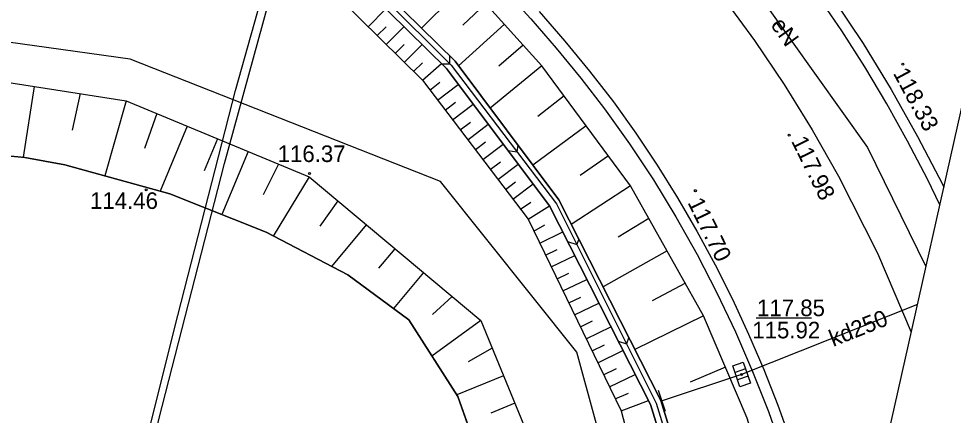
# Model space of a CAD drawing. Extents: x 6424617 to 6425697, y 5665845 to 5667190.
# Drawn here: x 6425523.12 to 6425565.32, y 5666883.53 to 5666901.46 of the extents above; entities that cross this region are included whole.
import ezdxf

# ---------------------------------------------------------------- set-up
doc = ezdxf.new("R2010")
doc.units = 0
for name, color, linetype in [('Warstwa 10', 7, 'Continuous'), ('Warstwa 12', 7, 'Continuous'), ('Warstwa 13', 7, 'Continuous'), ('Warstwa 14', 7, 'Continuous'), ('Warstwa 15', 7, 'Continuous'), ('Warstwa 2', 7, 'Continuous'), ('Warstwa 20', 7, 'Continuous'), ('Warstwa 21', 7, 'Continuous'), ('Warstwa 25', 7, 'Continuous'), ('Warstwa 4', 7, 'Continuous'), ('Warstwa 6', 7, 'Continuous'), ('Warstwa 63', 7, 'Continuous'), ('Warstwa 8', 7, 'Continuous'), ('Warstwa 9', 7, 'Continuous')]:
    doc.layers.add(name, color=color, linetype=linetype)

msp = doc.modelspace()

# ---------------------------------------------------------------- linework, layer by layer
at = {"layer": 'Warstwa 10'}
msp.add_lwpolyline([(6425511.502, 5666812.229), (6425512.943, 5666817.949), (6425515.607, 5666829.564), (6425516.724, 5666834.415), (6425518.245, 5666840.499), (6425520.445, 5666849.084), (6425523.479, 5666860.949), (6425527.047, 5666874.99), (6425530.311, 5666888.044), (6425532.912, 5666898.211), (6425534.329, 5666903.258)], dxfattribs=at)
at = {"layer": 'Warstwa 12'}
for points in [[(6425480.91, 5666946.73), (6425514.86, 5666932.41), (6425528.46, 5666925.91), (6425545.47, 5666915.06), (6425553.34, 5666907.03), (6425561.44, 5666895.63), (6425564.087, 5666890.255)], [(6425512.165, 5666813.402), (6425513.737, 5666820.109), (6425517.071, 5666834.688), (6425519.2, 5666843.022), (6425525.117, 5666866.017), (6425529.597, 5666883.929), (6425532.42, 5666894.918), (6425537.237, 5666912.487)], [(6425563.702, 5666888.538), (6425555.76, 5666885.38), (6425552.17, 5666884.18)]]:
    msp.add_lwpolyline(points, dxfattribs=at)
at = {"layer": 'Warstwa 14'}
msp.add_line((6425558.919, 5666887.928), (6425556.418, 5666887.928), dxfattribs=at)
msp.add_circle((6425555.76, 5666885.38), 0.045, dxfattribs=at)
at = {"layer": 'Warstwa 2'}
msp.add_lwpolyline([(6425506.88, 5666899.5), (6425503.781, 5666900.196), (6425486.964, 5666839.13), (6425494.478, 5666830.381), (6425496.276, 5666828.558), (6425500.644, 5666826.749), (6425510.918, 5666824.552), (6425520.412, 5666825.171), (6425529.858, 5666828.662), (6425537.889, 5666834.639), (6425544.658, 5666842.259), (6425549.605, 5666852.483), (6425550.773, 5666856.833), (6425551.852, 5666866.697), (6425550.934, 5666876.787), (6425548.326, 5666886.387), (6425542.173, 5666894.101), (6425528.149, 5666899.626), (6425515.187, 5666901.43), (6425512.303, 5666898.502), (6425510.878, 5666898.777)], dxfattribs=at)
at = {"layer": 'Warstwa 20'}
for points in [[(6425507.871, 5666925.02), (6425508.67, 5666920.18), (6425520.44, 5666914.46), (6425527.39, 5666910.43), (6425535.63, 5666904.32), (6425541.35, 5666898.67), (6425546.12, 5666892.4), (6425550.32, 5666883.74), (6425552.26, 5666876.31), (6425552.96, 5666866.55), (6425552.11, 5666856.38), (6425553.468, 5666853.734)], [(6425559.205, 5666868.481), (6425558.639, 5666873.647), (6425557.949, 5666876.96), (6425556.015, 5666883.397), (6425554.048, 5666888.034), (6425550.752, 5666893.896), (6425546.749, 5666899.32), (6425543.366, 5666903.082), (6425536.967, 5666908.8), (6425531.745, 5666912.645), (6425523.272, 5666917.6), (6425507.871, 5666925.02)], [(6425519.675, 5666899.039), (6425527.975, 5666897.748), (6425536.235, 5666894.308), (6425543.981, 5666887.816), (6425548.082, 5666877.839), (6425549.655, 5666866.937), (6425548.7, 5666857.221), (6425546.834, 5666855.804), (6425546.717, 5666855.426), (6425547.53, 5666853.351), (6425543.78, 5666845.666), (6425539.816, 5666839.966), (6425533.071, 5666833.755), (6425527.173, 5666830.091), (6425521.012, 5666827.921)]]:
    msp.add_lwpolyline(points, dxfattribs=at)
at = {"layer": 'Warstwa 21'}
msp.add_line((6425552.327, 5666883.705), (6425552.013, 5666884.655), dxfattribs=at)
for points in [[(6425553.468, 5666853.734), (6425554.21, 5666857.161), (6425554.915, 5666866.832), (6425553.95, 5666876.532), (6425551.644, 5666884.017), (6425547.085, 5666893.002), (6425542.435, 5666899.198), (6425536.342, 5666905.21), (6425528.1, 5666911.321), (6425521.083, 5666915.489), (6425508.96, 5666921.669), (6425509.189, 5666922.115)], [(6425536.669, 5666905.594), (6425542.822, 5666899.531), (6425547.51, 5666893.264), (6425552.118, 5666884.208), (6425554.442, 5666876.624), (6425555.416, 5666866.843), (6425554.709, 5666857.052), (6425553.912, 5666853.396), (6425552.033, 5666848.468), (6425548.678, 5666841.626), (6425544.206, 5666835.465), (6425537.121, 5666829.241), (6425528.009, 5666824.294), (6425519.824, 5666821.941)], [(6425520.41, 5666830.593), (6425526.02, 5666832.712), (6425530.6, 5666835.391), (6425534.418, 5666838.513), (6425537.253, 5666841.513), (6425540.2, 5666845.18), (6425542.652, 5666849.128), (6425544.489, 5666853.916), (6425545.767, 5666858.244), (6425546.686, 5666863.699), (6425546.684, 5666868.581), (6425546.075, 5666874.164), (6425544.861, 5666878.967), (6425542.948, 5666884.384), (6425540.73, 5666887.845), (6425537.986, 5666889.875), (6425534.289, 5666891.802), (6425529.949, 5666893.541), (6425525.201, 5666894.847), (6425523.397, 5666895.19), (6425517.355, 5666895.759)]]:
    msp.add_lwpolyline(points, dxfattribs=at)
at = {"layer": 'Warstwa 25'}
for centre in [(6425563.046, 5666899.396), (6425557.906, 5666896.187), (6425536.254, 5666894.459), (6425528.876, 5666893.723), (6425553.674, 5666893.683)]:
    msp.add_circle(centre, 0.045, dxfattribs=at)
at = {"layer": 'Warstwa 4'}
for p, q in [((6425555.938, 5666885.628), (6425555.466, 5666885.463)), ((6425556.054, 5666885.297), (6425555.582, 5666885.132))]:
    msp.add_line(p, q, dxfattribs=at)
msp.add_lwpolyline([(6425555.831, 5666885.935), (6425556.161, 5666884.991), (6425555.689, 5666884.825), (6425555.359, 5666885.769)], close=True, dxfattribs=at)
at = {"layer": 'Warstwa 6'}
for points in [[(6425545.074, 5666902.738), (6425546.253, 5666901.446), (6425547.396, 5666900.123), (6425548.504, 5666898.77), (6425549.575, 5666897.388), (6425550.705, 5666895.797), (6425551.779, 5666894.168), (6425552.794, 5666892.502), (6425553.751, 5666890.802), (6425554.649, 5666889.069), (6425555.485, 5666887.307), (6425556.259, 5666885.516), (6425556.97, 5666883.699), (6425557.618, 5666881.858), (6425557.174, 5666881.676), (6425557.47, 5666880.92), (6425557.987, 5666880.701), (6425558.37, 5666879.4), (6425558.722, 5666878.091), (6425559.042, 5666876.772), (6425559.33, 5666875.447), (6425559.585, 5666874.115), (6425559.808, 5666872.777), (6425559.947, 5666871.792)], [(6425564.713, 5666893.049), (6425564.15, 5666894.211), (6425563.257, 5666895.926), (6425562.314, 5666897.615), (6425561.322, 5666899.275), (6425560.282, 5666900.906), (6425559.291, 5666902.373)]]:
    msp.add_lwpolyline(points, dxfattribs=at)
at = {"layer": 'Warstwa 63'}
msp.add_lwpolyline([(6425341.164, 5665895.978), (6425588.9, 5667000.928), (6424898.307, 5667155.763), (6424650.57, 5666050.814)], close=True, dxfattribs=at)
at = {"layer": 'Warstwa 8'}
for p, q in [((6425554.927, 5666902.416), (6425556.345, 5666900.472)), ((6425559.901, 5666902.362), (6425561.246, 5666900.334)), ((6425546.623, 5666901.774), (6425547.775, 5666900.443)), ((6425547.775, 5666900.443), (6425548.891, 5666899.082)), ((6425556.345, 5666900.472), (6425557.689, 5666898.475)), ((6425561.246, 5666900.334), (6425562.516, 5666898.258)), ((6425548.891, 5666899.082), (6425549.971, 5666897.691)), ((6425557.689, 5666898.475), (6425558.955, 5666896.429)), ((6425562.516, 5666898.258), (6425563.71, 5666896.138)), ((6425549.971, 5666897.691), (6425550.98, 5666896.278)), ((6425550.98, 5666896.278), (6425551.945, 5666894.834)), ((6425558.955, 5666896.429), (6425560.143, 5666894.336)), ((6425563.71, 5666896.138), (6425564.827, 5666893.975)), ((6425517.355, 5666895.759), (6425523.397, 5666895.19)), ((6425523.397, 5666895.19), (6425525.201, 5666894.847)), ((6425525.201, 5666894.847), (6425529.949, 5666893.541)), ((6425551.945, 5666894.834), (6425552.865, 5666893.361)), ((6425560.143, 5666894.336), (6425561.892, 5666890.859)), ((6425564.827, 5666893.975), (6425564.891, 5666893.84)), ((6425529.949, 5666893.541), (6425534.289, 5666891.802)), ((6425552.865, 5666893.361), (6425553.739, 5666891.86)), ((6425553.739, 5666891.86), (6425554.567, 5666890.333)), ((6425534.289, 5666891.802), (6425537.986, 5666889.875)), ((6425561.892, 5666890.859), (6425563.421, 5666887.285)), ((6425554.567, 5666890.333), (6425555.347, 5666888.782)), ((6425537.986, 5666889.875), (6425540.73, 5666887.845)), ((6425555.347, 5666888.782), (6425556.079, 5666887.207)), ((6425540.73, 5666887.845), (6425542.948, 5666884.384)), ((6425556.079, 5666887.207), (6425556.762, 5666885.61)), ((6425556.762, 5666885.61), (6425557.396, 5666883.993)), ((6425542.948, 5666884.384), (6425544.861, 5666878.967)), ((6425557.396, 5666883.993), (6425557.981, 5666882.357))]:
    msp.add_line(p, q, dxfattribs=at)
at = {"layer": 'Warstwa 9'}
for p, q in [((6425536.611, 5666905.393), (6425542.642, 5666899.348)), ((6425543.366, 5666903.082), (6425541.31, 5666901.021)), ((6425544.212, 5666902.142), (6425543.177, 5666901.158)), ((6425538.899, 5666901.091), (6425539.698, 5666901.899)), ((6425545.058, 5666901.201), (6425542.974, 5666899.327)), ((6425539.308, 5666900.688), (6425539.707, 5666901.092)), ((6425539.716, 5666900.284), (6425540.515, 5666901.092)), ((6425540.124, 5666899.88), (6425540.524, 5666900.285)), ((6425540.533, 5666899.477), (6425541.333, 5666900.286)), ((6425545.904, 5666900.261), (6425544.797, 5666899.315)), ((6425540.942, 5666899.074), (6425541.356, 5666899.464)), ((6425541.35, 5666898.67), (6425542.207, 5666899.423)), ((6425542.209, 5666899.421), (6425542.569, 5666899.421)), ((6425542.57, 5666899.78), (6425542.569, 5666899.421)), ((6425542.642, 5666899.348), (6425547.397, 5666893.096)), ((6425546.749, 5666899.32), (6425544.408, 5666897.411)), ((6425541.69, 5666898.222), (6425542.139, 5666898.589)), ((6425523.825, 5666898.394), (6425523.328, 5666895.197)), ((6425542.031, 5666897.774), (6425542.968, 5666898.487)), ((6425525.9, 5666898.071), (6425525.536, 5666896.422)), ((6425527.975, 5666897.748), (6425527.018, 5666894.347)), ((6425547.75, 5666897.964), (6425546.562, 5666897.042)), ((6425542.372, 5666897.326), (6425542.839, 5666897.682)), ((6425542.713, 5666896.879), (6425543.644, 5666897.587)), ((6425529.352, 5666897.174), (6425528.806, 5666895.59)), ((6425530.728, 5666896.601), (6425529.504, 5666893.663)), ((6425543.054, 5666896.431), (6425543.518, 5666896.784)), ((6425543.394, 5666895.983), (6425544.319, 5666896.687)), ((6425548.75, 5666896.608), (6425546.34, 5666894.829)), ((6425532.105, 5666896.028), (6425531.502, 5666894.58)), ((6425543.735, 5666895.535), (6425544.196, 5666895.886)), ((6425544.076, 5666895.087), (6425544.995, 5666895.787)), ((6425545.656, 5666895.743), (6425545.615, 5666895.439)), ((6425533.482, 5666895.455), (6425532.294, 5666892.602)), ((6425545.215, 5666895.494), (6425545.615, 5666895.439)), ((6425549.751, 5666895.252), (6425548.478, 5666894.374)), ((6425534.858, 5666894.882), (6425534.155, 5666893.5)), ((6425544.416, 5666894.639), (6425544.875, 5666894.988)), ((6425544.757, 5666894.191), (6425545.671, 5666894.886)), ((6425536.235, 5666894.308), (6425534.61, 5666891.634)), ((6425545.098, 5666893.744), (6425545.553, 5666894.09)), ((6425545.439, 5666893.296), (6425546.346, 5666893.986)), ((6425550.752, 5666893.896), (6425548.071, 5666892.162)), ((6425537.526, 5666893.226), (6425536.726, 5666892.087)), ((6425545.78, 5666892.848), (6425546.248, 5666893.169)), ((6425547.397, 5666893.096), (6425551.903, 5666884.089)), ((6425546.12, 5666892.4), (6425547.088, 5666892.995)), ((6425551.576, 5666892.43), (6425550.183, 5666891.59)), ((6425538.817, 5666892.144), (6425537.241, 5666890.263)), ((6425546.382, 5666891.859), (6425546.884, 5666892.134)), ((6425546.645, 5666891.318), (6425547.683, 5666891.822)), ((6425548.408, 5666891.5), (6425548.323, 5666891.245)), ((6425540.108, 5666891.062), (6425539.374, 5666890.186)), ((6425546.908, 5666890.776), (6425547.432, 5666891.031)), ((6425547.906, 5666891.384), (6425548.323, 5666891.245)), ((6425547.17, 5666890.235), (6425548.228, 5666890.749)), ((6425552.4, 5666890.965), (6425549.507, 5666889.339)), ((6425541.399, 5666889.98), (6425540.038, 5666888.357)), ((6425547.432, 5666889.694), (6425547.966, 5666889.953)), ((6425547.695, 5666889.152), (6425548.772, 5666889.676)), ((6425553.224, 5666889.5), (6425551.726, 5666888.712)), ((6425542.69, 5666888.898), (6425541.8, 5666888.09)), ((6425547.958, 5666888.611), (6425548.501, 5666888.875)), ((6425548.22, 5666888.07), (6425549.317, 5666888.603)), ((6425554.048, 5666888.034), (6425550.947, 5666886.509)), ((6425543.981, 5666887.816), (6425541.78, 5666886.206)), ((6425548.482, 5666887.529), (6425549.036, 5666887.798)), ((6425548.745, 5666886.988), (6425549.861, 5666887.53)), ((6425550.188, 5666886.887), (6425550.566, 5666886.761)), ((6425550.666, 5666887.062), (6425550.566, 5666886.761)), ((6425544.494, 5666886.569), (6425543.417, 5666885.95)), ((6425549.008, 5666886.446), (6425549.57, 5666886.72)), ((6425549.27, 5666885.905), (6425550.406, 5666886.457)), ((6425549.532, 5666885.364), (6425550.106, 5666885.642)), ((6425555.032, 5666885.716), (6425553.435, 5666885.038)), ((6425545.006, 5666885.322), (6425542.901, 5666884.457)), ((6425549.795, 5666884.822), (6425550.951, 5666885.384)), ((6425550.058, 5666884.281), (6425550.655, 5666884.535)), ((6425545.519, 5666884.075), (6425544.44, 5666883.632)), ((6425550.32, 5666883.74), (6425551.554, 5666884.195)), ((6425551.903, 5666884.089), (6425554.198, 5666876.578))]:
    msp.add_line(p, q, dxfattribs=at)
for points in [[(6425553.468, 5666853.734), (6425554.21, 5666857.161), (6425554.915, 5666866.832), (6425553.95, 5666876.532), (6425551.644, 5666884.017), (6425547.085, 5666893.002), (6425542.435, 5666899.198), (6425536.342, 5666905.21), (6425528.1, 5666911.321), (6425521.083, 5666915.489), (6425508.96, 5666921.669), (6425509.189, 5666922.115), (6425507.871, 5666925.02), (6425508.67, 5666920.18), (6425520.44, 5666914.46), (6425527.39, 5666910.43), (6425535.63, 5666904.32), (6425541.35, 5666898.67), (6425546.12, 5666892.4), (6425550.32, 5666883.74), (6425552.26, 5666876.31), (6425552.96, 5666866.55), (6425552.11, 5666856.38)], [(6425553.912, 5666853.396), (6425554.709, 5666857.052), (6425555.416, 5666866.843), (6425554.442, 5666876.624), (6425552.118, 5666884.208), (6425547.51, 5666893.264), (6425542.822, 5666899.531), (6425536.669, 5666905.594), (6425528.377, 5666911.736), (6425521.331, 5666915.924), (6425509.189, 5666922.115), (6425508.96, 5666921.669), (6425521.083, 5666915.489), (6425528.1, 5666911.321), (6425536.342, 5666905.21), (6425542.435, 5666899.198), (6425547.085, 5666893.002), (6425551.644, 5666884.017), (6425553.95, 5666876.532), (6425554.915, 5666866.832), (6425554.21, 5666857.161), (6425553.468, 5666853.734)]]:
    msp.add_lwpolyline(points, close=True, dxfattribs=at)
for points in [[(6425536.669, 5666905.594), (6425542.822, 5666899.531), (6425547.51, 5666893.264), (6425552.118, 5666884.208), (6425554.442, 5666876.624), (6425555.416, 5666866.843), (6425554.709, 5666857.052), (6425553.912, 5666853.396), (6425552.033, 5666848.468), (6425548.678, 5666841.626), (6425544.206, 5666835.465), (6425537.121, 5666829.241), (6425528.009, 5666824.294), (6425519.824, 5666821.941)], [(6425559.205, 5666868.481), (6425558.639, 5666873.647), (6425557.949, 5666876.96), (6425556.015, 5666883.397), (6425554.048, 5666888.034), (6425550.752, 5666893.896), (6425546.749, 5666899.32), (6425543.366, 5666903.082)], [(6425519.675, 5666899.039), (6425527.975, 5666897.748), (6425536.235, 5666894.308), (6425543.981, 5666887.816), (6425548.082, 5666877.839), (6425549.655, 5666866.937), (6425548.7, 5666857.221), (6425546.834, 5666855.804), (6425546.717, 5666855.426), (6425547.53, 5666853.351), (6425543.78, 5666845.666), (6425539.816, 5666839.966), (6425533.071, 5666833.755), (6425527.173, 5666830.091), (6425521.012, 5666827.921)], [(6425520.41, 5666830.593), (6425526.02, 5666832.712), (6425530.6, 5666835.391), (6425534.418, 5666838.513), (6425537.253, 5666841.513), (6425540.2, 5666845.18), (6425542.652, 5666849.128), (6425544.489, 5666853.916), (6425545.767, 5666858.244), (6425546.686, 5666863.699), (6425546.684, 5666868.581), (6425546.075, 5666874.164), (6425544.861, 5666878.967), (6425542.948, 5666884.384), (6425540.73, 5666887.845), (6425537.986, 5666889.875), (6425534.289, 5666891.802), (6425529.949, 5666893.541), (6425525.201, 5666894.847), (6425523.397, 5666895.19), (6425517.355, 5666895.759)]]:
    msp.add_lwpolyline(points, dxfattribs=at)

# ---------------------------------------------------------------- texts
at = {"layer": 'Warstwa 13'}
for s, rotation, p in [('eN', 305.3922, (6425557.043, 5666901.171)), ('kd250', 21.6865, (6425559.897, 5666886.621))]:
    msp.add_text(s, height=0.75, rotation=rotation, dxfattribs=at).set_placement(p)
at = {"layer": 'Warstwa 14'}
msp.add_text('115.92', height=0.75, dxfattribs=at).set_placement((6425556.244, 5666887.009))
at = {"layer": 'Warstwa 15'}
msp.add_text('117.85', height=0.75, dxfattribs=at).set_placement((6425556.458, 5666888.013))
at = {"layer": 'Warstwa 25'}
for s, rotation, p in [('118.33', 298.299, (6425562.583, 5666898.995)), ('117.98', 296.2192, (6425557.988, 5666895.926)), ('117.70', 296.2192, (6425553.308, 5666893.149))]:
    msp.add_text(s, height=0.75, rotation=rotation, dxfattribs=at).set_placement(p)
for s, p in [('116.37', (6425534.814, 5666894.978)), ('114.46', (6425526.343, 5666892.858))]:
    msp.add_text(s, height=0.75, dxfattribs=at).set_placement(p)

doc.saveas('drawing.dxf')
